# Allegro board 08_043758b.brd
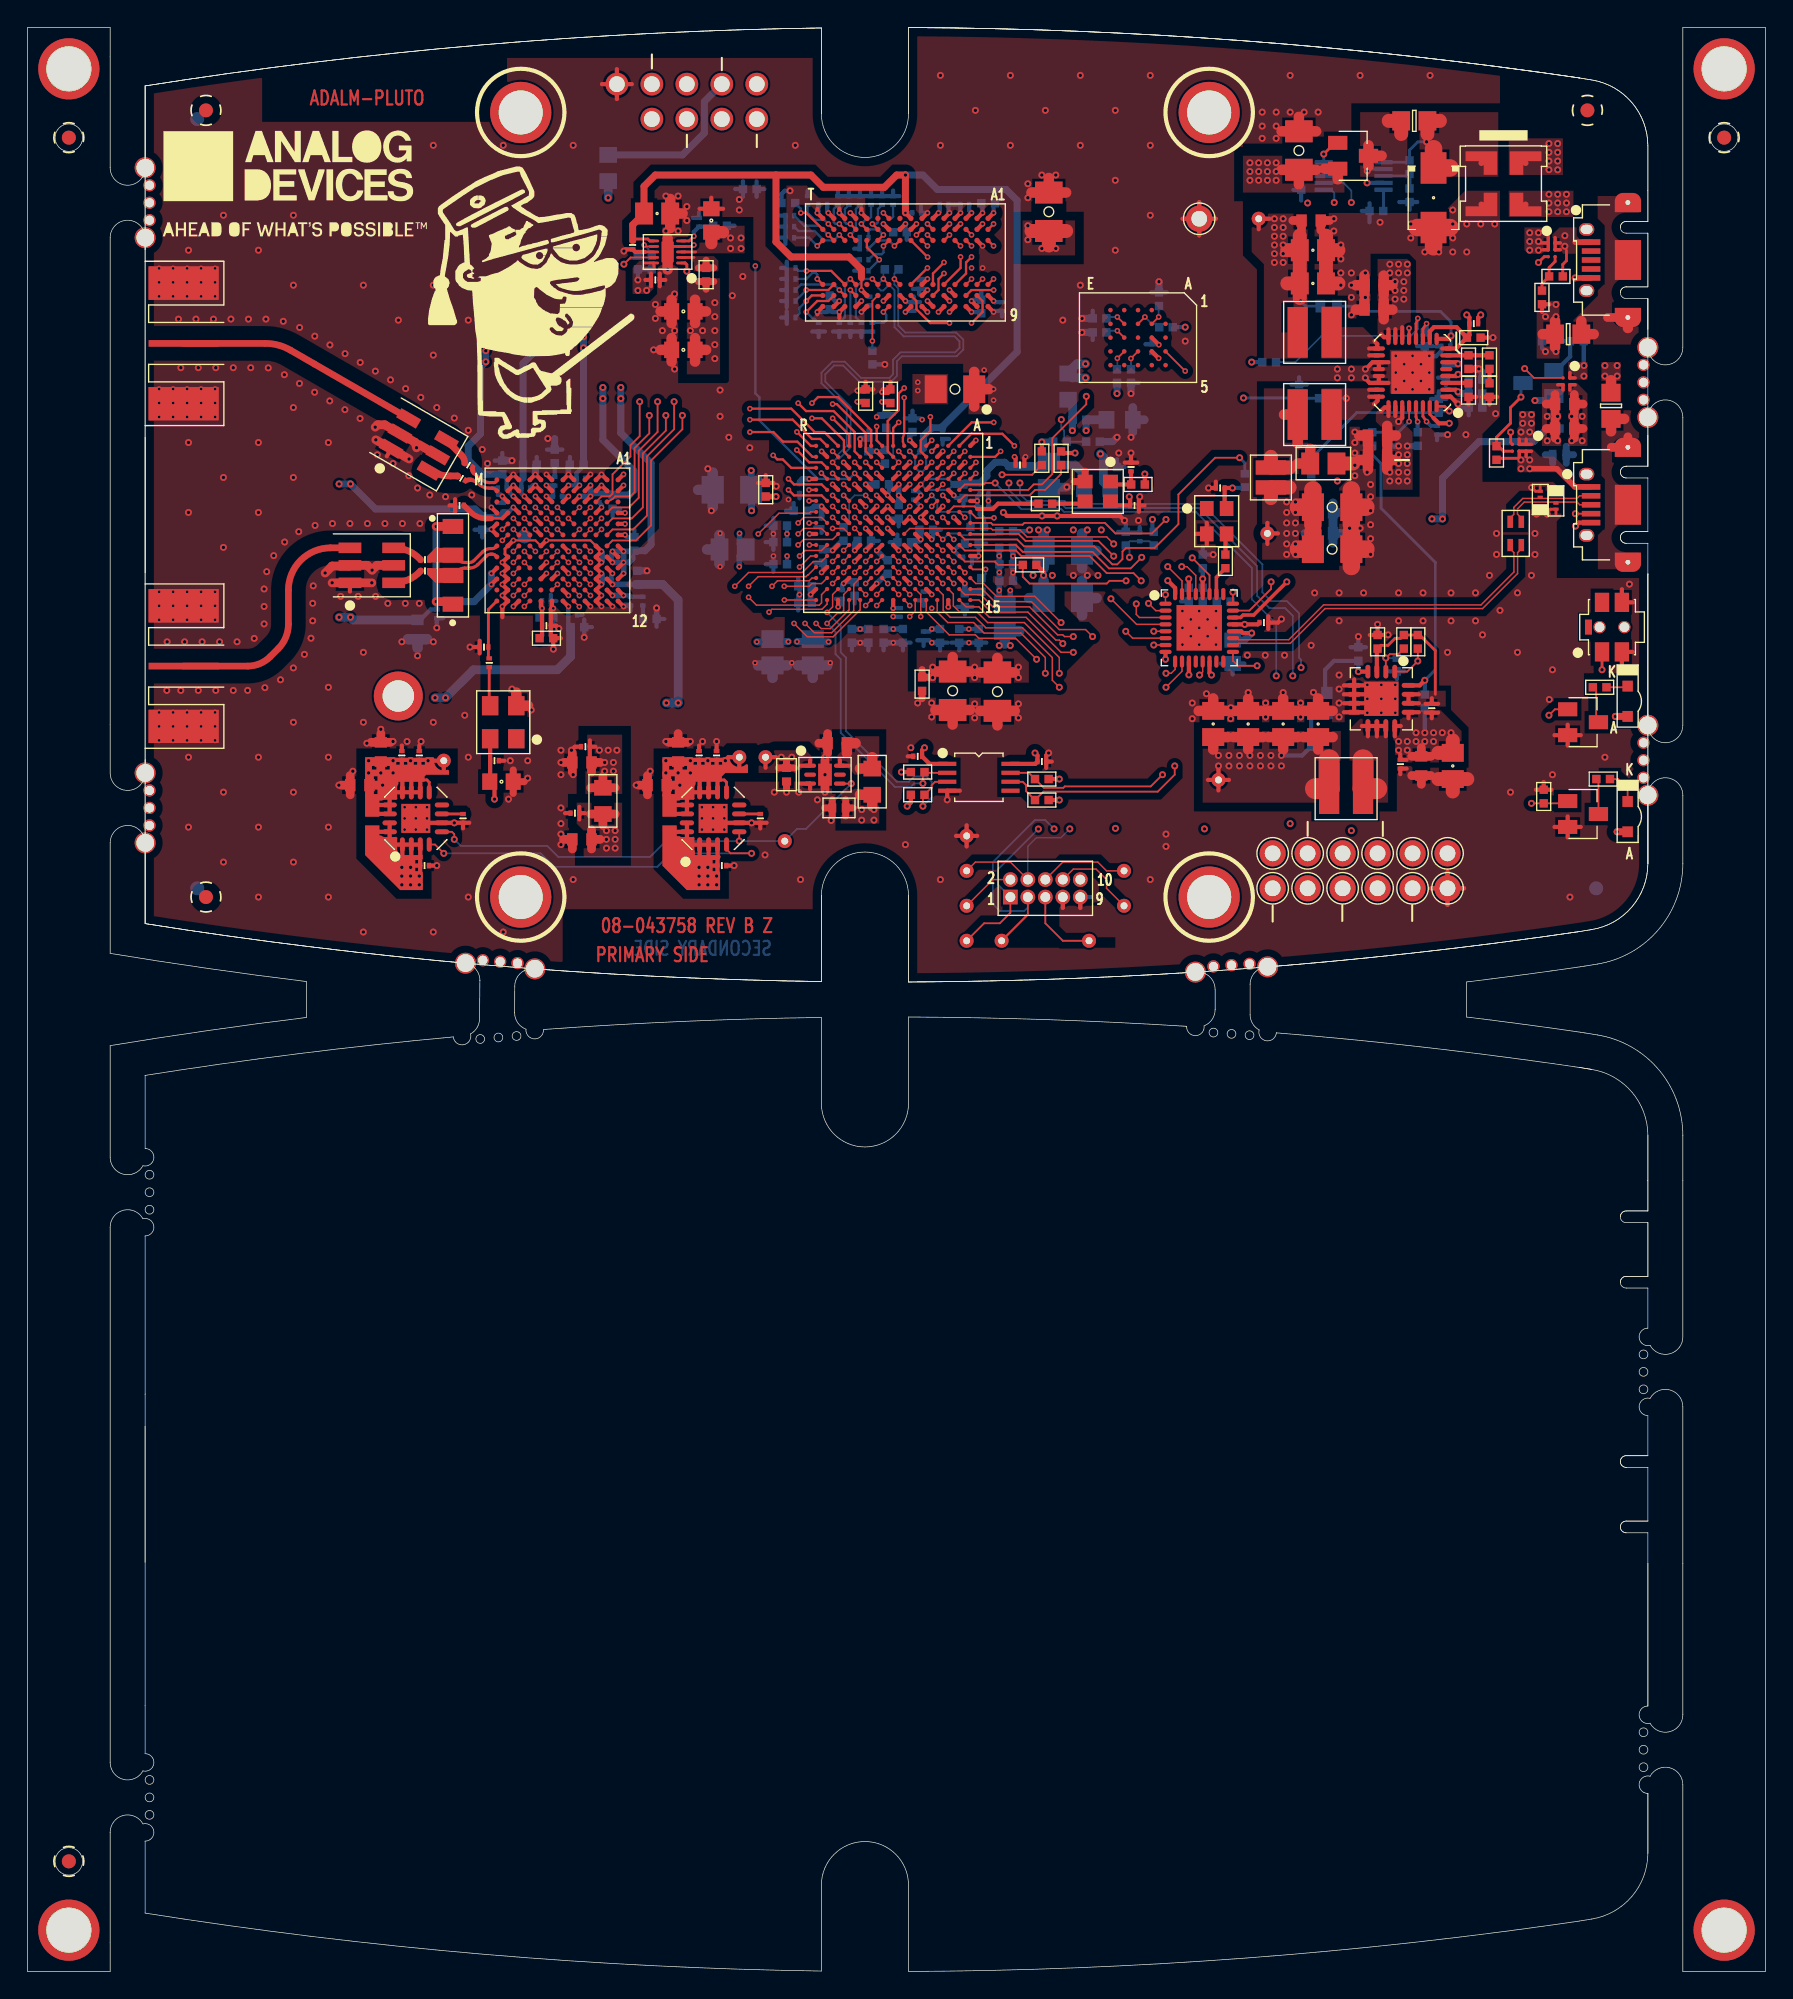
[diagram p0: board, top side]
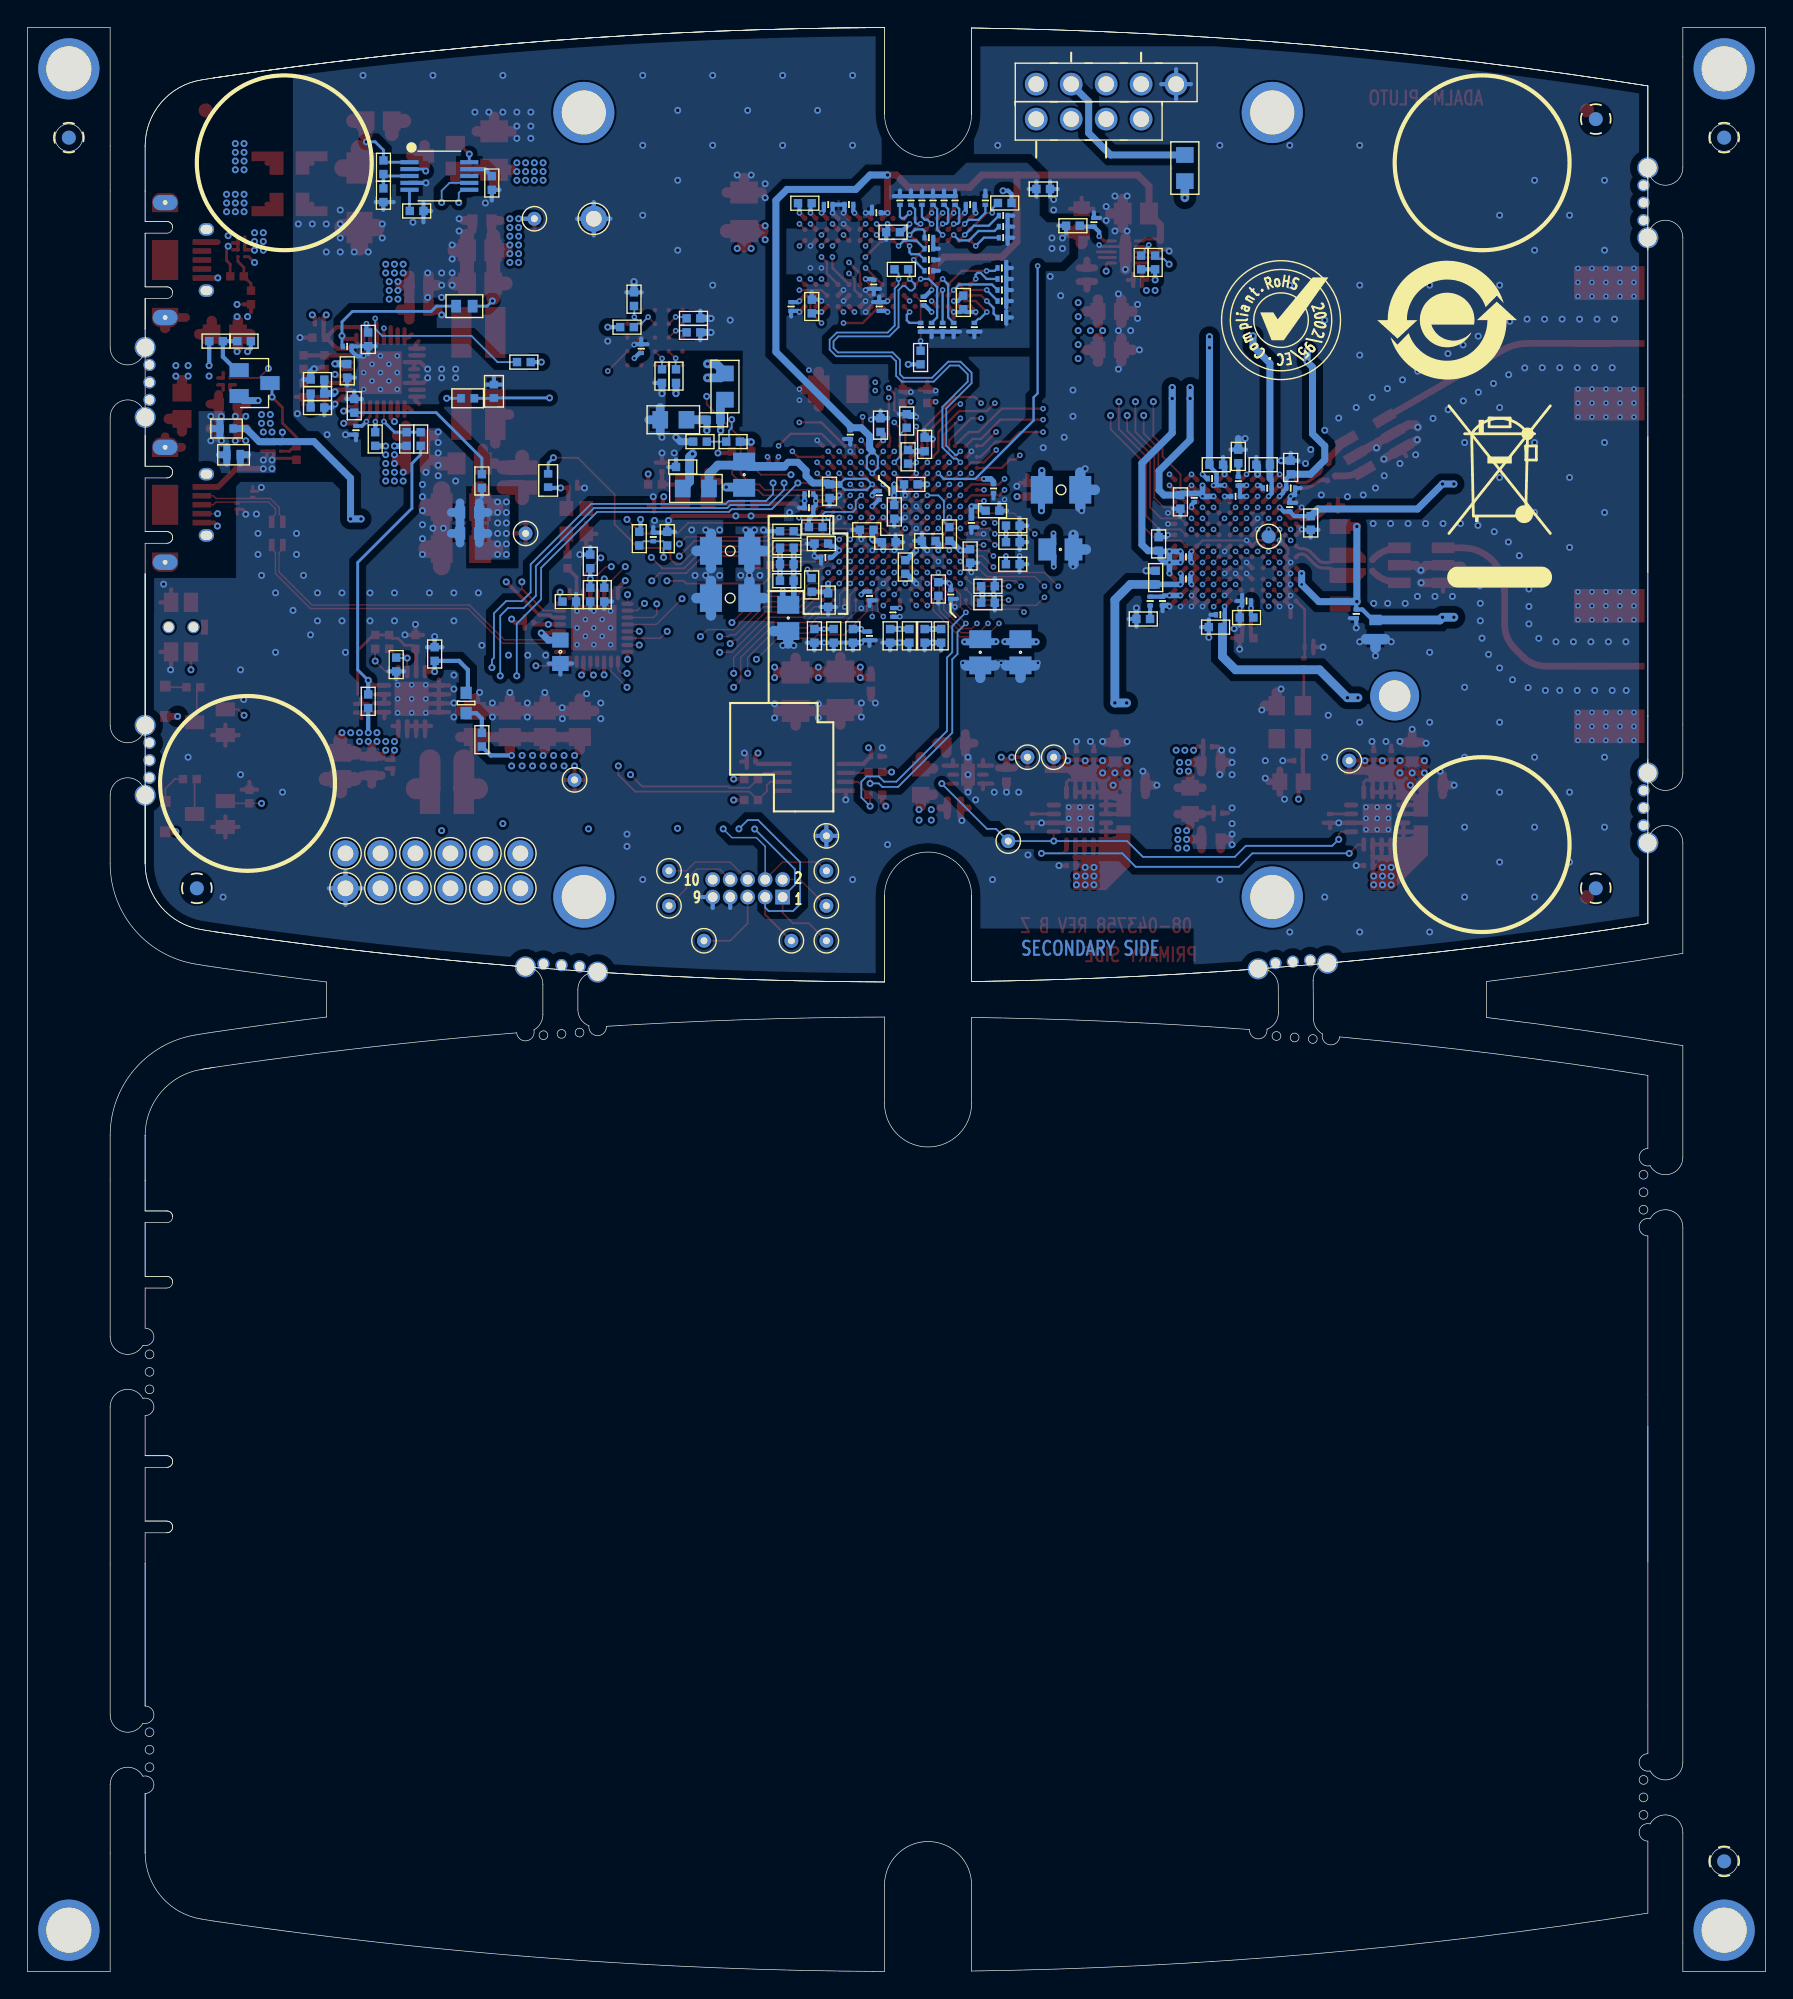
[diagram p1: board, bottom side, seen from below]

Outline 126.22 x 141.22 mm; copper layers: TOP, L2_GND, L3_PWR, L4_GND, L5_SIG, L6_SIG, L7_GND, L8_PWR, L9_GND, BOTTOM. Coordinates in mm from the lower left corner of the outline.

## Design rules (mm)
net group DDR3_CK: nets DDR3_CK_N DDR3_CK_P
net group DDR3_DQS0: nets DDR3_DQS0_N DDR3_DQS0_P
net group DDR3_DQS1: nets DDR3_DQS1_N DDR3_DQS1_P
net group DP1: nets UNNAMED_9_CHOKE4P_I327_N2 UNNAMED_9_CHOKE4P_I327_N3
net group RX1A: nets RX1A_N RX1A_P
net group TX1A: nets TX1A_N TX1A_P
net group UART: nets UART_RX UART_TX
net group USB_OTG: nets USB_OTG_N USB_OTG_P
net group CTRL_IN: nets CTRL_IN0 CTRL_IN1 CTRL_IN2 CTRL_IN3
net group CTRL_OUT: nets IO_L08_34_CTRL_OUT0 IO_L08_34_CTRL_OUT1 IO_L13_34_CTRL_OUT2 IO_L13_34_CTRL_OUT3 IO_L21_34_CTRL_OUT4 IO_L21_34_CTRL_OUT5 IO_L22_34_CTRL_OUT6 IO_L22_34_CTRL_OUT7
net group JTAG: nets JTAG_TCK JTAG_TDI JTAG_TDO JTAG_TMS
net group PWR: nets VCCPLL VDD33_USB VDDA1P1_RX_VCO VTTVREF
net group QSPI: nets PS_MIO01_500_QSPI0_SS_B PS_MIO02_500_QSPI0_IO0 PS_MIO03_500_QSPI0_IO1 PS_MIO04_500_QSPI0_IO2 PS_MIO05_500_QSPI0_IO3 PS_MIO06_500_QSPI0_SCLK
net group RF: nets UNNAMED_7_CAP_I39_N2 UNNAMED_7_CAP_I40_N2 UNNAMED_7_CAP_I51_N1 UNNAMED_7_CAP_I52_N1 UNNAMED_7_CNBNC5P_I57_CNTR UNNAMED_7_CNBNC5P_I58_CNTR
net group RX: nets IO_L01_34_RX_D0 IO_L01_34_RX_D1 IO_L02_34_RX_D2 IO_L02_34_RX_D3 IO_L03_34_RX_D4 IO_L03_34_RX_D5 IO_L04_34_RX_D6 IO_L04_34_RX_D7 IO_L05_34_RX_D8 IO_L05_34_RX_D9 IO_L06_34_RX_D10 IO_L06_34_RX_D11 IO_L07_34_RX_FRAME IO_L12_MRCC_34_DATA_CLK
net group SPI: nets IO_L23_35_SPI_CLK IO_L23_35_SPI_ENB IO_L24_35_SPI_DI IO_L24_35_SPI_DO
net group TX: nets IO_L01_34_FB_CLK IO_L09_34_TX_FRAME IO_L15_34_TX_D0 IO_L15_34_TX_D1 IO_L16_34_TX_D2 IO_L16_34_TX_D3 IO_L17_34_TX_D4 IO_L17_34_TX_D5 IO_L18_34_TX_D6 IO_L18_34_TX_D7 IO_L19_34_TX_D8 IO_L19_34_TX_D9 IO_L20_34_TX_D10 IO_L20_34_TX_D11
net group USB_ULPI: nets PS_MIO28_501_USB0_D4 PS_MIO29_501_USB0_DIR PS_MIO30_501_USB0_STP PS_MIO31_501_USB0_NXT PS_MIO32_501_USB0_D0 PS_MIO33_501_USB0_D1 PS_MIO34_501_USB0_D2 PS_MIO35_501_USB0_D3 PS_MIO36_501_USB0_CLK PS_MIO37_501_USB0_D5 PS_MIO38_501_USB0_D6 PS_MIO39_501_USB0_D7

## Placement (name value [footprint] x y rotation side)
AD9361_CLKOUT  TESTPAD  [TPSMC40]  36.09 104.25 180 bottom
ADC  613 001 111 21  [CNHDR1X1H344]  52.96 137.11 180 bottom
C1  0.1uF  [C0201]  28.83 80.34 0 top
C2  0.01uF  [C0201]  31.63 83.77 270 top
C3  10uF  [C0603]  24.13 86.18 180 top
C4  10uF  [C0603]  25.66 88.59 90 top
C5  0.1uF  [C0201]  27.18 88.34 90 top
C6  0.1uF  [C0201]  28.45 88.34 90 top
C7  0.1uF  [C0201]  102.37 111.96 90 bottom
C8  0.1uF  [C0201]  99.7 87.7 270 top
C9  10uF  [C0603]  101.22 87.58 270 top
C10  0.1uF  [C0201]  50.42 80.34 0 top
C11  47uF  [C0805H60]  103.51 87.58 270 top
C12  0.01uF  [C0201]  53.22 83.77 270 top
C13  0.1uF  [C0201#2]  98.05 96.59 90 top
C14  10uF  [C0603]  47.25 88.59 90 top
C15  10uF  [C0603]  45.72 86.18 180 top
C16  0.1uF  [C0201]  48.77 88.34 90 top
C17  47uF  [C0805H60]  91.19 90.62 90 top
C18  0.1uF  [C0201]  50.04 88.34 90 top
C19  47uF  [C0805H60]  86.11 90.62 90 top
C20  47uF  [C0805H60]  88.65 90.62 90 top
C21  47uF  [C0805H60]  93.73 90.62 90 top
C22  10uF  [C0603]  40.26 82.24 180 top
C23  0.01uF  [C0201]  40.19 108.46 0 bottom
C24  0.01uF  [C0201]  34.48 107.76 180 bottom
C25  0.1uF  [C0201]  39.75 84.15 180 top
C26  0.01uF  [C0201]  39.59 98.56 0 bottom
C27  0.01uF  [C0201]  42.08 102.76 180 bottom
C28  1uF  [C0402]  39.89 109.46 180 bottom
C29  1uF  [C0402]  34.48 109.26 90 bottom
C30  1uF  [C0402]  39.93 97.66 0 bottom
C31  1uF  [C0402]  44.07 103.71 90 bottom
C32  10uF  [C0603]  40.26 87.83 180 top
C33  0.1uF  [C0201]  40.52 88.97 180 top
C34  1uF  [C0402]  36.48 109.46 0 bottom
C35  1uF  [C0402]  44.29 101.26 90 bottom
C36  1uF  [C0402]  33.02 105.23 270 bottom
C37  1uF  [C0402]  42.49 106.76 270 bottom
C38  1uF  [C0402]  37.69 98.35 0 bottom
C39  0.01uF  [C0201]  36.18 107.76 0 bottom
C40  0.01uF  [C0201]  42.08 101.16 180 bottom
C41  0.01uF  [C0201]  34.55 106.37 90 bottom
C42  0.01uF  [C0201]  41.49 107.06 270 bottom
C43  0.01uF  [C0201]  37.68 97.76 0 top
C44  0.01uF  [C0201]  37.69 99.56 0 bottom
C45  1uF  [C0402]  37.68 96.86 0 top
C46  0.1uF  [C0201]  80.39 106.5 0 top
C47  0.1uF  [C0201]  80.78 104.21 90 bottom
C48  0.1uF  [C0201]  81.65 117.89 90 bottom
C49  100uF  [C1206H71]  75.19 103.2 0 bottom
C50  4.7uF  [C0402]  71.07 103.43 0 bottom
C51  0.47uF  [C0402]  56.14 106.12 180 bottom
C52  0.1uF  [C0201]  69.47 107.33 0 bottom
C53  0.01uF  [C0201]  69.47 106.33 0 bottom
C54  100uF  [C1206H71]  67.36 114.95 0 top
C55  4.7uF  [C0402]  64.27 112.33 90 bottom
C56  0.47uF  [C0402]  53.61 107.64 90 top
C57  0.47uF  [C0402]  62.67 114.43 90 top
C58  0.47uF  [C0402]  60.87 114.44 90 top
C59  0.47uF  [C0402]  61.07 110.93 90 bottom
C60  0.1uF  [C0201]  72.08 109.44 0 top
C61  0.01uF  [C0201]  56.06 107.73 270 bottom
C62  0.01uF  [C0201]  45.6 122.88 180 top
C63  0.01uF  [C0201]  64.57 127.76 180 bottom
C64  100uF  [C1206H71]  70.44 92.97 270 top
C65  47uF  [C0805H60]  57.03 95.83 270 bottom
C66  4.7uF  [C0402]  62.47 102.03 270 bottom
C67  4.7uF  [C0402]  61.07 97.03 270 bottom
C68  0.47uF  [C0402]  64.97 93.52 270 top
C69  0.47uF  [C0402]  68.57 103.73 0 bottom
C70  0.47uF  [C0402]  63.27 106.03 270 bottom
C71  100uF  [C1206H71]  67.19 93.04 270 top
C72  0.47uF  [C0402]  60.77 103.93 0 bottom
C73  4.7uF  [C0402]  62.07 108.03 0 bottom
C74  0.47uF  [C0402]  63.67 103.83 180 bottom
C75  0.47uF  [C0402]  65.27 104.73 0 bottom
C76  100uF  [C1206H71]  51.16 107.63 180 bottom
C77  47uF  [C0805H60]  51.21 103.3 180 bottom
C78  4.7uF  [C0402]  54.66 103.83 180 bottom
C79  10uF  [C0603#2]  49.66 127.2 90 top
C80  0.01uF  [C0201]  48.77 127.07 90 bottom
C81  0.22UF  [C0805]  45.72 127.71 0 top
C82  10uF  [C0603#2]  47.63 117.8 180 top
C83  10uF  [C0603#2]  47.63 120.6 180 top
C84  0.01uF  [C0201]  43.95 125.42 270 top
C85  47uF  [C0805H60]  74.18 108.73 270 bottom
C86  4.7uF  [C0402]  58.26 121.25 270 bottom
C87  4.7uF  [C0402]  69.27 120.95 90 bottom
C88  0.47uF  [C0402]  69.77 128.46 180 bottom
C89  0.47uF  [C0402]  63.36 126.35 0 bottom
C90  0.47uF  [C0402]  54.66 105.03 180 bottom
C91  0.1uF  [C0201]  64.36 120.95 90 bottom
C92  0.1uF  [C0201]  64.76 122.55 270 bottom
C93  0.47uF  [C0402]  76.4 112.72 0 bottom
C94  0.1uF  [C0201]  68.06 128.36 180 bottom
C95  0.1uF  [C0201]  66.56 128.36 0 bottom
C96  0.1uF  [C0201]  57.76 128.35 180 bottom
C97  0.1uF  [C0201]  70.77 120.95 270 bottom
C98  0.1uF  [C0201]  64.37 107.23 90 bottom
C99  0.01uF  [C0201]  66.46 111.65 90 bottom
C100  100uF  [C1206H71]  74.17 127.84 90 top
C101  4.7uF  [C0402]  52.45 129.49 180 bottom
C102  0.01uF  [C0201]  61.16 121.35 270 bottom
C103  47uF  [C0805H60]  70.97 98.33 270 bottom
C104  47uF  [C0805H60]  54.11 95.83 270 bottom
C105  4.7uF  [C0402]  63.57 97.03 270 bottom
C106  4.7uF  [C0402]  59.87 97.03 270 bottom
C107  4.7uF  [C0402]  69.07 97.03 270 bottom
C108  4.7uF  [C0402]  54.67 102.23 180 bottom
C109  0.47uF  [C0402]  62.17 97.03 270 bottom
C110  0.47uF  [C0402]  60.07 100.43 270 bottom
C111  0.47uF  [C0402]  68.07 99.62 270 bottom
C112  0.47uF  [C0402]  56.47 100.63 180 bottom
C113  0.47uF  [C0402]  67.67 97.03 270 bottom
C114  0.47uF  [C0402]  56.47 99.43 180 bottom
C115  0.47uF  [C0402]  66.28 97.03 270 bottom
C116  0.47uF  [C0402]  57.76 102.83 270 bottom
C117  0.1uF  [C0201]  65.07 97.03 270 bottom
C118  0.1uF  [C0201]  59.17 100.03 270 bottom
C119  0.01uF  [C0201]  63.37 98.73 270 bottom
C120  0.01uF  [C0201]  57.67 105.23 270 bottom
C121  10uF  [C0603#2]  34.42 86.43 0 top
C122  0.1uF  [C0201]  33.91 87.96 0 top
C123  18pF  [C0201]  33.53 95.07 90 top
C124  18pF  [C0201]  33.15 96.21 180 top
C125  0.001uF  [C0201]  38.48 107.16 180 bottom
C126  1uF  [C0402]  38.28 110.06 270 bottom
C127  1uF  [C0402]  45.19 98.25 0 bottom
C128  0.001uF  [C0201]  43.79 99.55 270 bottom
C129  0.001uF  [C0201]  29.72 98.63 90 bottom
C130  10uF  [C0603]  28.32 97.48 270 bottom
C131  18pF  [C0201]  28.86 101.74 180 top
C132  18pF  [C0201]  28.86 102.56 180 top
C133  18pF  [C0201]  31.52 108.47 330 top
C134  18pF  [C0201]  32.03 109.43 330 top
C135  10uF  [C0603]  98.05 111.58 180 top
C136  10uF  [C0603]  97.79 120.72 180 top
C137  10uF  [C0603]  98.05 109.8 180 top
C138  10uF  [C0603]  97.79 122.5 180 top
C139  0.047uF  [C0402]  101.48 118.56 90 bottom
C140  1uF  [C0402]  85.35 102.44 90 bottom
C141  1uF  [C0402]  105.03 118.69 0 top
C142  150pF  [C0402]  105.16 115.64 180 bottom
C143  180pF  [C0402]  104.65 116.91 90 top
C144  0.0033uF  [C0402]  106.18 116.91 270 top
C145  47uF  [C0805H60]  93.35 125.04 0 top
C146  22uF  [C0805H53]  94.11 109.55 0 top
C147  0.0056uF  [C0402]  105.16 113.61 0 bottom
C148  47uF  [C0805H60]  93.35 122.63 0 top
C149  100uF  [C1206H71]  94.75 103.32 0 top
C150  100uF  [C1206H71]  94.75 106.37 0 top
C151  10uF  [C0603]  93.22 127.2 0 top
C152  10uF  [C0603]  94.11 105.99 0 bottom
C153  10uF  [C0603]  94.11 104.47 0 bottom
C154  1uF  [C0402]  84.33 100.02 270 bottom
C155  0.047uF  [C0402]  92.5 129.93 270 bottom
C156  0.47uF  [C0402]  97.96 127.89 180 bottom
C157  100uF  [C1206H71]  92.33 132.28 90 top
C158  100uF  [C1206H71]  75.19 99.77 0 bottom
C159  4.7uF  [C0402]  71.07 102.23 0 bottom
C160  0.47uF  [C0402]  71.07 101.03 0 bottom
C161  0.1uF  [C0201]  65.07 99.93 270 bottom
C162  0.01uF  [C0201]  68.27 102.73 0 bottom
C163  0.1uF  [C0201]  86.62 107.77 0 top
C164  0.1uF  [C0201]  89.79 97.99 0 top
C165  2.2uF  [C0603#2]  87.52 95.87 270 bottom
C166  0.1uF  [C0201]  64.65 88.27 0 top
C167  0.1uF  [C0201]  73.66 87.89 0 top
C168  1uF  [C0402]  85.35 100.02 270 bottom
C169  1uF  [C0402]  58.93 84.53 180 top
C170  1uF  [C0402]  55.12 86.94 270 top
C171  2.2uF  [C0603]  111.64 113.87 180 top
C172  2.2uF  [C0603]  111.64 112.09 180 top
C173  10uF  [C0603]  58.8 89.23 180 top
C174  4.7uF  [C0402]  78.63 109.29 0 bottom
C178  0.47uF  [C0402]  67.98 107.54 270 bottom
D1  SESD0201X1UN-0020-09  [D0201]  111 106.45 270 top
D2  SESD0201X1UN-0020-09  [D0201]  109.86 107.31 90 top
D3  SMAJ5A  [DIOSMJ5_0]  102.11 128.85 270 top
DAC1  613 001 111 21  [CNHDR1X1H344]  45.34 137.11 180 bottom
DAC2  613 001 111 21  [CNHDR1X1H344]  45.34 134.57 180 bottom
DS1  LTST-S220TBKT  [LED0804]  116.21 92.28 270 top
DS2  LTST-S220TBKT  [LED0804]  116.21 83.89 270 top
E1  100OHM  [L0805]  77.68 107.73 180 bottom
E2  100OHM  [L0805]  61.34 86.43 90 top
E3  100OHM  [L0805]  42.17 131.01 270 bottom
E4  100OHM  [L0805]  41.79 85.04 90 top
E5  100OHM  [L0805]  75.57 115.14 270 bottom
E6  100OHM  [L0805]  79.32 112.72 180 bottom
F1  0.5A  [F0402H20]  111.26 110.18 180 bottom
GND  TESTPAD  [unnamed#3]  68.2 82.5 180 bottom
GND#2  613 001 111 21  [unnamed#3]  42.8 137.11 180 bottom
GND#3  WP45  [unnamed#3]  85.09 127.33 180 bottom
GND#4  WP45  [unnamed#3]  103.13 78.69 180 bottom
GPO0  613 001 111 21  [CNHDR1X1H344]  52.96 134.57 180 bottom
GPO1  613 001 111 21  [CNHDR1X1H344]  50.42 134.57 180 bottom
GPO2  613 001 111 21  [CNHDR1X1H344]  47.88 134.57 180 bottom
GPO3  613 001 111 21  [CNHDR1X1H344]  47.88 137.11 180 bottom
JTAG_BOOT  TESTPAD  [TPSMC40]  77.09 74.88 180 bottom
L2  1.5uH  [LSMSQ157H83]  93.48 119.07 180 top
L3  1.5uH  [LSMSQ157H83]  93.48 113.1 180 top
L4  1uH  [LSMSQ157H83]  95.76 85.93 180 top
L5  270NH  [LSMSQ79H41]  90.3 108.53 270 top
L6  90OHMS AT 100MEGHZ  [L0805-4PH39]  108.08 104.47 90 top
L7  800OHMS AT 100MEGHZ  [L2020_A]  107.19 129.87 180 top
L8  330NH  [L0805-F]  30.9 100.37 90 top
L9  330NH  [L0805-F]  30.9 103.93 270 top
L10P  WP45  [TPC75D45]  90.43 78.69 180 bottom
L12N  WP45  [TPC75D45]  92.97 78.69 180 bottom
L24N  WP45  [TPC75D45]  90.43 81.23 180 bottom
MIO0  WP45  [TPC75D45]  100.59 81.23 180 bottom
MIO09  WP45  [TPC75D45]  98.05 78.69 180 bottom
MIO10  WP45  [TPC75D45]  100.59 78.69 180 bottom
MIO11  WP45  [TPC75D45]  98.05 81.23 180 bottom
MIO48  WP45  [TPC75D45]  92.97 81.23 180 bottom
MIO49  WP45  [TPC75D45]  95.51 78.69 180 bottom
MIO53  WP45  [TPC75D45]  95.51 81.23 180 bottom
NOREF  -  [unnamed]  117.36 116.71 0 top
NOREF#2  -  [unnamed]  3 3 180 top
NOREF#3  -  [#2]  7.27 125.95 0 top
NOREF#4  -  [#2]  -91.18 -74.35 0 top
NOREF#5  -  [unnamed]  34.33 73.36 0 top
NOREF#6  -  [#2]  -91.18 -74.35 0 top
NOREF#7  -  [unnamed]  8.86 127.22 0 top
NOREF#8  -  [#2]  7.27 10.11 0 top
NOREF#9  -  [unnamed]  90.06 72.98 0 top
NOREF#10  -  [unnamed]  117.36 86.72 0 top
NOREF#11  -  [unnamed]  123.22 138.22 180 top
NOREF#12  -  [#2]  3 138.22 0 top
NOREF#13  -  [unnamed]  8.86 129.76 0 top
NOREF#14  -  [#2]  403.09 237.99 0 top
NOREF#15  -  [unnamed]  35.58 73.25 0 top
NOREF#16  -  [unnamed]  8.86 128.49 0 top
NOREF#17  -  [unnamed]  31.81 73.25 0 top
NOREF#18  -  [#2]  3 3 0 top
NOREF#19  -  [#2]  0 0 0 top
NOREF#20  -  [unnamed]  87.44 73.11 0 top
NOREF#21  -  [#2]  8.54 4.24 0 top
NOREF#22  -  [unnamed]  8.86 83.26 0 top
NOREF#23  -  [#2]  7.27 15.19 0 top
NOREF#24  -  [unnamed]  117.36 115.44 0 top
NOREF#25  -  [unnamed]  12.96 135.2 0 top
NOREF#26  -  [unnamed]  117.36 114.17 0 top
NOREF#27  -  [#2]  104.5 69.34 0 top
NOREF#28  -  [unnamed]  35.82 78.05 180 top
NOREF#29  -  [unnamed]  113.29 135.2 0 top
NOREF#30  -  [#2]  -80.18 88.52 0 top
NOREF#31  -  [unnamed]  26.93 92.66 0 top
NOREF#32  -  [unnamed]  117.68 90.53 0 top
NOREF#33  -  [unnamed]  33.07 73.46 0 top
NOREF#34  -  [unnamed]  117.68 112.9 0 top
NOREF#35  -  [#2]  7.27 87.07 0 top
NOREF#36  -  [unnamed]  36.84 72.83 0 top
NOREF#37  -  [unnamed]  8.86 84.53 0 top
NOREF#38  -  [unnamed]  84.82 72.6 0 top
NOREF#39  -  [unnamed]  85.82 135.05 180 top
NOREF#40  -  [#2]  7.27 59.15 0 top
NOREF#41  -  [#2]  126.22 0 90 top
NOREF#42  -  [#2]  0 141.22 0 top
NOREF#43  -  [#2]  7.27 81.99 0 top
NOREF#44  -  [unnamed]  35.82 135.05 180 top
NOREF#45  -  [unnamed]  86.13 73.01 0 top
NOREF#46  -  [#2]  123.22 3 0 top
NOREF#47  -  [unnamed]  117.36 87.99 0 top
NOREF#48  -  [#2]  19.43 129.87 0 top
NOREF#49  -  [#2]  124.53 139.17 0 top
NOREF#50  -  [#2]  -91.18 -74.35 0 top
NOREF#51  -  [#2]  6 0 0 top
NOREF#52  -  [unnamed]  3 133.22 0 top
NOREF#53  -  [unnamed]  12.96 78.05 0 top
NOREF#54  -  [unnamed]  123.22 3 180 top
NOREF#55  -  [#2]  3 3 0 top
NOREF#56  -  [#2]  120.22 0 0 top
NOREF#57  -  [#2]  126.22 0 0 top
NOREF#58  -  [unnamed]  117.36 89.26 0 top
NOREF#59  -  [unnamed]  8.54 81.99 0 top
NOREF#60  -  [#2]  7.27 54.07 0 top
NOREF#61  -  [#2]  210.84 143.3 0 top
NOREF#62  -  [#2]  0 141.22 0 top
NOREF#63  -  [unnamed]  8.54 131.03 0 top
NOREF#64  -  [#2]  36.58 121.23 0 top
NOREF#65  -  [#2]  0 0 0 top
NOREF#66  -  [unnamed]  3 8 0 top
NOREF#67  -  [unnamed]  88.75 73.2 0 top
NOREF#68  -  [unnamed]  3 138.22 180 top
NOREF#69  -  [unnamed]  8.54 125.95 0 top
NOREF#70  -  [unnamed]  85.82 78.05 180 top
NOREF#71  -  [#2]  117.68 8.61 0 top
NOREF#72  -  [unnamed]  123.22 133.22 0 top
NOREF#73  -  [#2]  -29.22 306.96 0 top
NOREF#74  -  [unnamed]  117.68 85.45 0 top
NOREF#75  -  [#2]  7.27 131.03 0 top
NOREF#76  -  [unnamed]  8.54 87.07 0 top
NOREF#77  -  [#2]  20.27 69.31 0 top
NOREF#78  -  [#2]  124.21 133.37 0 top
NOREF#79  -  [unnamed]  8.86 85.8 0 top
NOREF#80  -  [unnamed]  117.68 117.98 0 top
NOREF#81  -  [unnamed]  12.32 134.57 180 bottom
NOREF#82  -  [#2]  23.12 119.96 180 bottom
NOREF#83  -  [unnamed]  3 8 180 bottom
NOREF#84  -  [unnamed]  3 133.22 180 bottom
NOREF#85  -  [#2]  35.18 119.96 180 bottom
NOREF#86  -  [unnamed]  113.92 78.69 180 bottom
NOREF#87  -  [#2]  10.04 117.42 180 bottom
NOREF#88  -  [unnamed]  123.22 133.22 180 bottom
NOREF#89  -  [unnamed]  12.32 78.69 180 bottom
P1  FTSH-105-01-L-D  [CNHDR2X5H219]  71.38 78.05 0 top
P2  47590-0001  [CNMOLEX47590-0001]  117.68 106.55 180 top
P3  47590-0001  [CNMOLEX47590-0001]  117.68 124.33 180 top
PG_1P3V  TESTPAD  [TPSMC40]  54.99 82.12 180 bottom
Q1  BSS138LT1G  [SOT23]  112.97 90.75 270 top
Q2  BSS138LT1G  [SOT23]  109.73 115.39 270 bottom
Q3  SI2304DDS-T1-GE3  [SOT23]  96.27 131.9 270 top
Q4  BSS138LT1G  [SOT23]  112.97 84.08 270 top
R1  10  [R0201]  101.98 91.77 270 top
R2  27.4K  [R0402]  96.65 95.7 270 bottom
R3  46.4K  [R0402]  99.44 94.94 90 bottom
R4  17.8K  [R0603]  94.36 92.15 270 bottom
R5  0  [R0402]  100.97 96.59 270 top
R6  10K  [R0402]  101.48 92.28 90 bottom
R7  1K  [R0402]  93.22 89.48 270 bottom
R8  10K  [R0402]  80.65 108.02 180 top
R9  10K  [R0201]  80.14 109.29 90 top
R10  0  [R0402]  99.95 96.59 270 top
R11  4.7K  [R0402]  74.98 111.14 0 bottom
R12  39  [R0402]  73.92 106.63 180 top
R13  20K  [R0402]  81.79 104.09 270 bottom
R14  240  [R0402]  82.68 119.45 180 bottom
R15  0  [R0402]  79.76 104.09 90 bottom
R16  120  [R0201]  60.46 128.65 90 bottom
R17  120  [R0201]  55.36 126.76 180 bottom
R18  120  [R0201]  55.45 122.15 180 bottom
R19  120  [R0201]  57.46 119.45 270 bottom
R20  120  [R0201]  55.46 120.15 180 bottom
R21  120  [R0201]  60.56 119.45 270 bottom
R22  120  [R0201]  55.46 123.75 180 bottom
R23  120  [R0201]  59.66 128.65 90 bottom
R24  120  [R0201]  58.86 128.65 90 bottom
R25  120  [R0201]  56.66 128.65 90 bottom
R26  120  [R0201]  55.36 127.56 180 bottom
R27  120  [R0201]  55.45 121.35 180 bottom
R28  120  [R0201]  58.96 119.45 270 bottom
R29  120  [R0201]  55.46 122.95 180 bottom
R30  120  [R0201]  59.76 119.45 270 bottom
R31  120  [R0201]  60.76 125.95 180 bottom
R32  120  [R0201]  60.76 124.35 180 bottom
R33  120  [R0201]  62.86 128.65 90 bottom
R34  120  [R0201]  55.36 125.95 180 bottom
R35  120  [R0201]  61.26 128.65 90 bottom
R36  120  [R0201]  60.76 123.55 180 bottom
R37  120  [R0201]  60.76 125.15 180 bottom
R38  120  [R0201]  61.36 119.45 270 bottom
R39  120  [R0201]  62.06 128.65 90 bottom
R40  240  [R0402]  62.37 112.63 90 bottom
R41  240  [R0402]  62.27 110.03 90 bottom
R42  1K  [R0402]  55.25 128.47 180 bottom
R43  0  [R0402]  50.3 126.82 180 bottom
R44  0  [R0402]  49.28 123.26 90 top
R45  0  [R0402]  68.97 104.93 180 bottom
R46  4.7K  [R0402]  59.27 104.43 270 bottom
R47  4.7K  [R0402]  73.66 109.93 90 top
R48  470  [R0402]  114.18 93.29 180 top
R49  14.3K  [R0201]  31.37 106.5 0 top
R50  100K  [R0402]  90.17 116.91 180 bottom
R51  1  [R0201]  38.28 108.26 270 bottom
R52  1  [R0201]  44.69 99.55 270 bottom
R53  27.4K  [R0402]  104.65 114.88 90 top
R54  4.7K  [R0402]  103 116.28 270 bottom
R55  1K  [R0805]  115 113.74 90 top
R56  10  [R0201]  105.03 119.71 180 top
R57  20K  [R0402]  88.41 108.31 90 bottom
R58  1K  [R0805]  111.89 118.95 180 top
R59  100K  [R0402]  100.97 111.33 270 bottom
R60  10K  [R0402]  105.16 114.63 0 bottom
R61  10K  [R0402]  106.18 114.88 90 top
R62  17.8K  [R0603#2]  94.49 120.98 0 bottom
R63  14.3K  [R0201]  103 118.06 180 bottom
R64  46.4K  [R0402]  93.22 108.28 270 bottom
R65  23.2K  [R0402]  102.49 113.74 270 bottom
R66  240  [R0402]  112.53 118.44 180 bottom
R67  10K  [R0402]  110.49 118.44 180 bottom
R68  10K  [R0402]  111 123.14 180 top
R69  10K  [R0402]  109.99 121.61 270 top
R70  10K  [R0402]  106.68 110.31 90 top
R71  10K  [R0402]  100.37 131.07 270 bottom
R72  10K  [R0402]  100.37 129.04 270 bottom
R73  0.05  [R0805]  100.71 134.44 180 top
R74  10K  [R0402]  72.77 102.18 180 top
R75  10K  [R0402]  110.11 85.35 90 top
R76  20K  [R0402]  69.27 100.73 90 bottom
R77  8.06K  [R0402]  86.87 99.51 180 bottom
R78  4.7K  [R0402]  64.65 85.48 0 top
R79  4.7K  [R0402]  64.65 87.13 0 top
R80  4.7K  [R0402]  73.66 85.1 180 top
R81  4.7K  [R0402]  73.66 86.62 180 top
R82  39  [R0402]  87 102.44 90 top
R83  20K  [R0402]  71.07 104.63 180 bottom
R84  20K  [R0402]  75.06 109.93 90 top
R85  0  [R0402]  98.68 111.33 90 bottom
R86  0  [R0402]  97.67 111.33 90 bottom
R87  470  [R0402]  114.43 86.62 180 top
R88  1K  [R0402]  111.76 112.09 180 bottom
R89  4.7K  [R0402]  94.25 114.28 180 bottom
R90  1K  [R0402]  92.35 114.79 90 bottom
R91  4.7K  [R0402]  77.38 111.14 0 bottom
R116  20K  [R0402]  82.17 121.49 90 bottom
R119  20K  [R0402]  77.85 120.09 180 bottom
R120  20K  [R0402]  77.85 119.07 180 bottom
R121  20K  [R0402]  80.14 115.9 270 bottom
R122  20K  [R0402]  79.12 115.9 270 bottom
R142  80.6  [R0402]  62.76 123.65 180 bottom
R165  240  [R0402]  61.36 117.25 270 bottom
R221  10K  [R0402]  44.33 124.15 90 bottom
R222  10K  [R0402]  45.34 124.15 90 bottom
RX  TESTPAD  [TPSMC40]  68.2 74.88 180 bottom
RX1A  JCCEM001  [CNSMARAL687W375H171]  11.08 118.27 180 top
S1  PTS840 GKP SMTR LFS  [SWSML140W138H55]  115.07 97.66 0 top
T1  TCM1-63AX+  [TSML150W160H160]  28.42 110.93 60 top
T5  TCM1-63AX+  [TSML150W160H160]  25 102.15 90 top
TCK  TESTPAD  [TPSMC40]  68.2 79.96 180 bottom
TDI  TESTPAD  [TPSMC40]  79.63 77.42 180 bottom
TDO  TESTPAD  [TPSMC40]  79.63 79.96 180 bottom
TMS  TESTPAD  [TPSMC40]  68.2 77.42 180 bottom
TX  TESTPAD  [TPSMC40]  70.74 74.88 180 bottom
TX1A  JCCEM001  [CNSMARAL687W375H171]  11.08 94.83 180 top
U1  ADP1754ACPZ-1.3  [QFN16_4X4_PAD2_1X2_1]  28.2 83.77 0 top
U2  MT41K256M16TW-107 IT:P  [FBGA96_C]  63.76 124.15 180 top
U3  ADP2164ACPZ  [QFN16_4X4_PAD2_5X2_5]  98.32 92.45 180 top
U4  XC7Z010-1CLG225C  [CSPBGA225]  62.87 105.23 180 top
U5  AD9363ABCZ  [BGA144-2]  38.48 103.96 180 top
U6  ADP2114ACPZ  [QFN32_5X5_PAD3_1X3_1]  100.59 116.15 90 top
U7  ADP1754ACPZ-1.3  [QFN16_4X4_PAD2_1X2_1]  49.79 83.77 0 top
U8  NCP339AFCT2G  [WLCSP6]  110.69 125.07 270 top
U9  NCP339AFCT2G  [WLCSP6]  108.33 110.69 180 top
U10  ADM1177-1ARMZ  [RM10]  96.31 130.43 270 bottom
U11  TCA9517DGKR  [MSOP8]  69.09 86.75 270 top
U12  ADM7160ACPZN1.8  [DFN6_2X2_PAD1_6X1]  57.92 86.94 270 top
U13  MT25QU256ABA8E12-1SIT  [TBGA24]  80.65 118.69 180 top
U14  TPS51206DSQR  [SON10_2X2_PAD1_5X0_9]  46.49 124.91 90 top
U15  USB3320C-EZK  [QFN32_5X5_PAD3_3X3_3]  85.09 97.61 270 top
U16  ADP198ACBZ-11  [WLCSP4-2]  111.76 115.52 180 top
UNK1P0V  TESTPAD  [TPSMC40]  86.49 86.56 180 bottom
UNK1P3V_A  TESTPAD  [TPSMC40]  51.69 88.21 180 bottom
UNK1P3V_B  TESTPAD  [TPSMC40]  30.23 87.96 180 bottom
UNK1P8V_CLK  TESTPAD  [TPSMC40]  53.6 88.21 180 bottom
UNK1V8  TESTPAD  [TPSMC40]  103.13 81.23 180 bottom
UNK1V8#2  TESTPAD  [TPSMC40]  90.05 104.47 180 bottom
UNK1V35  TESTPAD  [TPSMC40]  89.41 127.33 180 bottom
VDD_GPO  613 001 111 21  [CNHDR1X1H344]  50.42 137.11 180 bottom
Y1  24MEGHZ  [YSML98W79H35]  86.36 105.36 270 top
Y2  33.333MEGHZ  [YSML98W79H35]  77.73 107.52 180 top
Y3  40MEGHz  [YSML126W98H47]  34.55 90.75 90 top

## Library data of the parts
AD9361_CLKOUT JTAG_BOOT PG_1P3V RX TCK TDI TDO TMS TX UNK1P0V UNK1P3V_A UNK1P3V_B UNK1P8V_CLK UNK1V8 UNK1V35 = NCTESTPAD: Tolerance: N/A; User Part Number: UPN; alternate symbols: (); part number: NCTESTPAD_SM-TESTPAD,E019801,TPSMC40; tolerance: N/A
ADC DAC1 DAC2 GPO0-GPO3 VDD_GPO = CN1P: User Part Number: UPN; Tolerance: N/A; alternate symbols: (); part number: CN1P_TH-613 001 111 21,E016125,CNHDR1X1H344; tolerance: N/A
C1 C5-C8 C10 C16 C18 C25 C33 C46-C48 C52 C60 C91 C92 C94-C98 C117 C118 C122 C161 C163 C164 C166 C167 = CAP: User Part Number: UPN; Tolerance: 20; part number: CAP_SM-0.1UF,16V,20,E017331,C0201; tolerance: 20
C2 C12 C23 C24 C26 C27 C39-C44 C53 C61-C63 C80 C84 C99 C102 C119 C120 C162 = CAP: User Part Number: UPN; Tolerance: 10; part number: CAP_SM-0.01UF,10V,10,E007201,C0201; tolerance: 10
C3 C4 C9 C14 C15 C22 C32 C79 C82 C83 C121 C130 C135-C138 C151-C153 C173 = CAP: Tolerance: 20; User Part Number: UPN; alternate symbols: C0603L_ALT; part number: CAP_SM-10UF,6.3V,20,E007143,C0603; tolerance: 20
C11 C17 C19-C21 C65 C77 C85 C103 C104 C145 C148 = CAP: Tolerance: 20; User Part Number: UPN; alternate symbols: (); part number: CAP_SM-47UF,6.3V,20,E008247,C0805H60; tolerance: 20
C13 = CAP: Tolerance: 20; User Part Number: UPN; alternate symbols: C0402_ALT; part number: CAP_SM-0.1UF,16V,20,E017331,C0201; tolerance: 20
C28-C31 C34-C38 C45 C127 C140 C141 C154 C168 = CAP: Tolerance: 10; User Part Number: UPN; alternate symbols: C0402_ALT; part number: CAP_SM-1UF,6.3V,10,E007449,C0402; tolerance: 10
C49 C54 C64 C71 C76 C100 C149 C150 C157 C158 = CAP: Tolerance: 20; User Part Number: UPN; part number: CAP_SM-100UF,6.3V,20,E016591,C1206H71; tolerance: 20
C50 C55 C66 C67 C73 C78 C86 C87 C101 C105-C108 C159 C174 = CAP: Tolerance: 10; User Part Number: UPN; alternate symbols: C0402_ALT; part number: CAP_SM-4.7UF,6.3V,10,E020089,C0402; tolerance: 10
C51 C56-C59 C68-C70 C72 C74 C75 C88-C90 C93 C109-C116 C156 C160 C178 = CAP: Tolerance: 10; User Part Number: UPN; alternate symbols: C0402_ALT; part number: CAP_SM-0.47UF,10V,10,E007611,C0402; tolerance: 10
C81 = CAP: Tolerance: 10; User Part Number: UPN; part number: CAP_SM-0.22UF,16V,10,E000443,C0805; tolerance: 10
C123 C124 C131-C134 = CAP: User Part Number: UPN; Tolerance: 5; part number: CAP_SM-18PF,50V,5,E017960,C0201; tolerance: 5
C125 C128 C129 = CAP: User Part Number: UPN; Tolerance: 10; alternate symbols: (); part number: CAP_SM-0.001UF,25V,10,E006762,C0201; tolerance: 10
C126 = CAP: Tolerance: 10; User Part Number: UPN; alternate symbols: R0402_ALT; part number: CAP_SM-1UF,6.3V,10,E007449,C0402; tolerance: 10
C139 C155 = CAP: Tolerance: 10; User Part Number: UPN; alternate symbols: C0402_ALT; part number: CAP_SM-0.047UF,25V,10,E006454,C0402; tolerance: 10
C142 = CAP: Tolerance: 5; User Part Number: UPN; alternate symbols: C0402_ALT; part number: CAP_SM-150PF,50V,5,E012646,C0402; tolerance: 5
C143 = CAP: Tolerance: 5; User Part Number: UPN; alternate symbols: C0402_ALT; part number: CAP_SM-180PF,50V,5,E012612,C0402; tolerance: 5
C144 = CAP: Tolerance: 10; User Part Number: UPN; alternate symbols: C0402_ALT; part number: CAP_SM-0.0033UF,50V,10,E007461,C0402; tolerance: 10
C146 = CAP: Tolerance: 20; User Part Number: UPN; alternate symbols: (); part number: CAP_SM-22UF,6.3V,20,E006534,C0805H53; tolerance: 20
C147 = CAP: Tolerance: 10; User Part Number: UPN; alternate symbols: C0402_ALT; part number: CAP_SM-0.0056UF,25V,10,E011820,C0402; tolerance: 10
C165 = CAP: Tolerance: 10; User Part Number: UPN; alternate symbols: (); part number: CAP_SM-2.2UF,16V,10,E020871,C0603; tolerance: 10
C169 C170 = CAP: Tolerance: 10; User Part Number: UPN; alternate symbols: (); part number: CAP_SM-1UF,6.3V,10,E007449,C0402; tolerance: 10
C171 C172 = CAP: Tolerance: 10; User Part Number: UPN; alternate symbols: C0603L_ALT; part number: CAP_SM-2.2UF,16V,10,E020871,C0603; tolerance: 10
D1 D2 = DIO: Tolerance: N/A; User Part Number: UPN; alternate symbols: (); part number: DIO_SM-SESD0201X1UN-0020-09,9V,N/A,E022225,D0201; tolerance: N/A
D3 = DIO: Tolerance: N/A; User Part Number: UPN; alternate symbols: (); part number: DIO_SM-SMAJ5A,5V,N/A,E001108,DIOSMJ5_0; tolerance: N/A
DS1 DS2 = DIOLED: User Part Number: UPN; Tolerance: N/A; alternate symbols: LED0804_RA; part number: DIOLED_SM-LTST-S220TBKT,3.3V,N/A,E026167,LED0804; tolerance: N/A
E1-E6 = FERRITE: Tolerance: 25; User Part Number: UPN; alternate symbols: (); part number: FERRITE_SM-100OHM,25,E012241,L0805; tolerance: 25
F1 = FSFUSE: User Part Number: UPN; Tolerance: N/A; alternate symbols: (); part number: FSFUSE_SM-0.5A,6V,E023876,F0402H20; tolerance: N/A
GND GND#3 GND#4 UNK1V8#2 = -: Tolerance: N/A; User Part Number: UPN
GND#2 = -: User Part Number: UPN; Tolerance: N/A
L2 L3 = IND: User Part Number: UPN; Tolerance: 20; alternate symbols: (); part number: IND_SM-1.5UH,20,E017267,LSMSQ157H83; tolerance: 20
L4 = IND: User Part Number: UPN; Tolerance: 20; alternate symbols: (); part number: IND_SM-1UH,20,E015845,LSMSQ157H83; tolerance: 20
L5 = IND: User Part Number: UPN; Tolerance: 20; alternate symbols: (); part number: IND_SM-270NH,20,E027278,LSMSQ79H41; tolerance: 20
L6 = CHOKE4P: User Part Number: UPN; Tolerance: 25; alternate symbols: (); part number: CHOKE4P_SM-90OHMS AT 100MEGHZ,25,E027226,L0805-4PH39; tolerance: 25
L7 = CHOKE4P: User Part Number: UPN; Tolerance: N/A; alternate symbols: (); part number: CHOKE4P_SM-800OHMS AT 100MEGHZ,N/A,E027130,L2020_A; tolerance: N/A
L8 L9 = IND: Tolerance: 5; User Part Number: UPN; part number: IND_SM-330NH,5,E006599,L0805-F; tolerance: 5
L10P L12N L24N MIO0 MIO09-MIO11 MIO48 MIO49 MIO53 = NCWP: Tolerance: N/A; User Part Number: UPN; alternate symbols: (); part number: NCWP_TH-WP45,E002516,TPC75D45; tolerance: N/A
P1 = CN10P_ODD_EVEN: Tolerance: N/A; User Part Number: UPN; part number: CN10P_ODD_EVEN_TH-FTSH-105-01-L-D,E018623,CNHDR2X5H219; tolerance: N/A
P2 P3 = CN5P_3SHLD: User Part Number: UPN; Tolerance: N/A; alternate symbols: (); part number: CN5P_3SHLD_SM-47590-0001,E015753,CNMOLEX47590-0001; tolerance: N/A
Q1 Q2 Q4 = TRANNMOSFET_V8: User Part Number: UPN; Tolerance: N/A; part number: TRANNMOSFET_V8_SM-BSS138LT1G,E018770,SOT23; tolerance: N/A
Q3 = TRANTN0200T: User Part Number: UPN; Tolerance: N/A; alternate symbols: (); part number: TRANTN0200T_SM-SI2304DDS-T1-GE3,E014916,SOT23; tolerance: N/A
R1 R56 = RES: User Part Number: UPN; Tolerance: 1; part number: RES_SM-10,E013982,1/20W,1,R0201; tolerance: 1
R2 R53 = RES: Tolerance: 1; User Part Number: UPN; alternate symbols: R0402_ALT; part number: RES_SM-27.4K,E021819,1/10W,1,R0402; tolerance: 1
R3 R64 = RES: Tolerance: 1; User Part Number: UPN; alternate symbols: R0402_ALT; part number: RES_SM-46.4K,E011115,1/16W,1,R0402; tolerance: 1
R4 = RES: Tolerance: 1; User Part Number: UPN; alternate symbols: R0603_A; part number: RES_SM-17.8K,E011033,1/10W,1,R0603; tolerance: 1
R5 R10 R15 R43-R45 R85 R86 = RES: Tolerance: 1; User Part Number: UPN; alternate symbols: R0402_ALT; part number: RES_SM-0,E010661,1/16W,1,R0402; tolerance: 1
R6 R8 R60 R61 R67-R72 R74 R75 R221 R222 = RES: Tolerance: 1; User Part Number: UPN; alternate symbols: R0402_ALT; part number: RES_SM-10K,E003751,1/16W,1,R0402; tolerance: 1
R7 R42 = RES: Tolerance: 1; User Part Number: UPN; alternate symbols: R0402_ALT; part number: RES_SM-1K,E003763,1/10W,1,R0402; tolerance: 1
R9 = RES: User Part Number: UPN; Tolerance: 1; part number: RES_SM-10K,E004011,1/20W,1,R0201; tolerance: 1
R11 R46 R47 R54 R78-R81 R89 R91 = RES: Tolerance: 1; User Part Number: UPN; alternate symbols: R0402_ALT; part number: RES_SM-4.7K,E008190,1/16W,1,R0402; tolerance: 1
R12 R82 = RES: Tolerance: 5; User Part Number: UPN; alternate symbols: R0402_ALT; part number: RES_SM-39,E003441,1/16W,5,R0402; tolerance: 5
R13 R57 R76 R83 R84 R116 R119-R122 = RES: Tolerance: 1; User Part Number: UPN; alternate symbols: R0402_ALT; part number: RES_SM-20K,E003791,1/16W,1,R0402; tolerance: 1
R14 R40 R41 R66 R165 = RES: Tolerance: 1; User Part Number: UPN; alternate symbols: R0402_ALT; part number: RES_SM-240,E010877,1/16W,1,R0402; tolerance: 1
R16-R39 = RES: User Part Number: UPN; Tolerance: 1; part number: RES_SM-120,E011549,1/20W,1,R0201; tolerance: 1
R48 R87 = RES: Tolerance: 5; User Part Number: UPN; alternate symbols: R0402_ALT; part number: RES_SM-470,E017765,1/10W,5,R0402; tolerance: 5
R49 R63 = RES: User Part Number: UPN; Tolerance: 1; part number: RES_SM-14.3K,E014068,1/20W,1,R0201; tolerance: 1
R50 R59 = RES: Tolerance: 1; User Part Number: UPN; alternate symbols: R0402_ALT; part number: RES_SM-100K,E003796,1/16W,1,R0402; tolerance: 1
R51 R52 = RES: User Part Number: UPN; part number: RES_SM-1,E014056,1/20W,1,R0201
R55 R58 = RES: Tolerance: 1; User Part Number: UPN; alternate symbols: (); part number: RES_SM-1K,E023448,1/3W,1,R0805; tolerance: 1
R62 = RES: Tolerance: 1; User Part Number: UPN; alternate symbols: R0603L; part number: RES_SM-17.8K,E011033,1/10W,1,R0603; tolerance: 1
R65 = RES: Tolerance: 1; User Part Number: UPN; alternate symbols: R0402_ALT; part number: RES_SM-23.2K,E019517,1/16W,1,R0402; tolerance: 1
R73 = RES: Tolerance: 1; User Part Number: UPN; alternate symbols: (); part number: RES_SM-0.05,E013377,1/8W,1,R0805; tolerance: 1
R77 = RES: Tolerance: 1; User Part Number: UPN; alternate symbols: R0402_ALT; part number: RES_SM-8.06K,E021385,1/10W,1,R0402; tolerance: 1
R88 R90 = RES: Tolerance: 1; User Part Number: UPN; alternate symbols: (); part number: RES_SM-1K,E003763,1/10W,1,R0402; tolerance: 1
R142 = RES: Tolerance: 0.1; User Part Number: UPN; alternate symbols: R0402_ALT; part number: RES_SM-80.6,E022369,1/16W,0.1,R0402; tolerance: 0.1
RX1A TX1A = CNBNC5P: User Part Number: UPN; Tolerance: N/A; alternate symbols: (); part number: CNBNC5P_SM-JCCEM001,E027545,CNSMARAL687W375H171; tolerance: N/A
S1 = SWSPST5P_V2: User Part Number: UPN; Tolerance: N/A; alternate symbols: (); part number: SWSPST5P_V2_SM-PTS840 GKP SMTR LFS,E024294,SWSML140W138H55; tolerance: N/A
T1 T5 = XFMRTCMXXXX_V3: Tolerance: N/A; User Part Number: UPN; part number: XFMRTCMXXXX_V3_SM-TCM1-63AX+,E018203,TSML150W160H160; tolerance: N/A
U1 U7 = ADP1754: Tolerance: N/A; User Part Number: UPN; alternate symbols: (); part number: ADP1754_SM-ADP1754ACPZ-1.3,E022696,QFN16_4X4_PAD2_1X2_1; tolerance: N/A
U2 = ICMT41K256M16: User Part Number: UPN; Tolerance: N/A; alternate symbols: (); part number: ICMT41K256M16_SM-MT41K256M16TW-107 IT:P,E025601,FBGA96_C; tolerance: N/A
U3 = ADP2164: Tolerance: N/A; User Part Number: UPN; alternate symbols: (); part number: ADP2164_SM-ADP2164ACPZ,E013699,QFN16_4X4_PAD2_5X2_5; tolerance: N/A
U4 = ICXC7Z010: Tolerance: N/A; User Part Number: UPN; alternate symbols: (); part number: ICXC7Z010_SM-XC7Z010-1CLG225C,E025809,CSPBGA225; tolerance: N/A
U5 = AD9363: Tolerance: N/A; User Part Number: UPN; part number: AD9363_SM-AD9363ABCZ,E026056,BGA144-2; tolerance: N/A
U6 = ADP2114: User Part Number: UPN; Tolerance: N/A; alternate symbols: (); part number: ADP2114_SM-ADP2114ACPZ,E008105,QFN32_5X5_PAD3_1X3_1; tolerance: N/A
U8 U9 = ICNCP339: Tolerance: N/A; User Part Number: UPN; alternate symbols: (); part number: ICNCP339_SM-NCP339AFCT2G,E025896,WLCSP6; tolerance: N/A
U10 = ADM1177: Tolerance: N/A; User Part Number: UPN; alternate symbols: (); part number: ADM1177_SM-ADM1177-1ARMZ,E016506,RM10; tolerance: N/A
U11 = CMOSTCA9517: Tolerance: N/A; User Part Number: UPN; alternate symbols: (); part number: CMOSTCA9517_SM-TCA9517DGKR,E022173,MSOP8; tolerance: N/A
U12 = ADM7160_V2: User Part Number: UPN; Tolerance: N/A; alternate symbols: (); part number: ADM7160_V2_SM-ADM7160ACPZN1.8,E018693,DFN6_2X2_PAD1_6X1; tolerance: N/A
U13 = ICMT25Q: User Part Number: UPN; Tolerance: N/A; alternate symbols: (); part number: ICMT25Q_SM-MT25QU256ABA8E12-1SIT,E027529,TBGA24; tolerance: N/A
U14 = ICTPS51206: Tolerance: N/A; User Part Number: UPN; alternate symbols: (); part number: ICTPS51206_SM-TPS51206DSQR,E021346,SON10_2X2_PAD1_5X0_9; tolerance: N/A
U15 = ICUSB3320C: Tolerance: N/A; User Part Number: UPN; alternate symbols: (); part number: ICUSB3320C_SM-USB3320C-EZK,E021334,QFN32_5X5_PAD3_3X3_3; tolerance: N/A
U16 = ADP198: Tolerance: N/A; User Part Number: UPN; alternate symbols: (); part number: ADP198_SM-ADP198ACBZ-11,E024730,WLCSP4-2; tolerance: N/A
Y1 = XTALOSC4P_V7: Tolerance: N/A; User Part Number: UPN; alternate symbols: (); part number: XTALOSC4P_V7_SM-24MEGHZ,E022374,YSML98W79H35; tolerance: N/A
Y2 = XTALOSC4P_V7: Tolerance: N/A; User Part Number: UPN; part number: XTALOSC4P_V7_SM-33.333MEGHZ,E024048,YSML98W79H35; tolerance: N/A
Y3 = XTALOSC4P_V21: Tolerance: N/A; User Part Number: UPN; part number: XTALOSC4P_V21_SM-40MEGHZ,E020493,YSML126W98H47; tolerance: N/A

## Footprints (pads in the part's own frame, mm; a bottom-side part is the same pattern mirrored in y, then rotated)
BGA144-2
  round 0.356 smd: A1(-4.4,-4.4) A2(-4.4,-3.6) A3(-4.4,-2.8) A4(-4.4,-2) A5(-4.4,-1.2) A6(-4.4,-0.4) A7(-4.4,0.4) A8(-4.4,1.2) A9(-4.4,2) A10(-4.4,2.8) A11(-4.4,3.6) A12(-4.4,4.4) B1(-3.6,-4.4) B2(-3.6,-3.6) B3(-3.6,-2.8) B4(-3.6,-2) B5(-3.6,-1.2) B6(-3.6,-0.4) B7(-3.6,0.4) B8(-3.6,1.2) B9(-3.6,2) B10(-3.6,2.8) B11(-3.6,3.6) B12(-3.6,4.4) C1(-2.8,-4.4) C2(-2.8,-3.6) C3(-2.8,-2.8) C4(-2.8,-2) C5(-2.8,-1.2) C6(-2.8,-0.4) C7(-2.8,0.4) C8(-2.8,1.2) C9(-2.8,2) C10(-2.8,2.8) C11(-2.8,3.6) C12(-2.8,4.4) D1(-2,-4.4) D2(-2,-3.6) D3(-2,-2.8) D4(-2,-2) D5(-2,-1.2) D6(-2,-0.4) D7(-2,0.4) D8(-2,1.2) D9(-2,2) D10(-2,2.8) D11(-2,3.6) D12(-2,4.4) E1(-1.2,-4.4) E2(-1.2,-3.6) E3(-1.2,-2.8) E4(-1.2,-2) E5(-1.2,-1.2) E6(-1.2,-0.4) E7(-1.2,0.4) E8(-1.2,1.2) E9(-1.2,2) E10(-1.2,2.8) E11(-1.2,3.6) E12(-1.2,4.4) F1(-0.4,-4.4) F2(-0.4,-3.6) F3(-0.4,-2.8) F4(-0.4,-2) F5(-0.4,-1.2) F6(-0.4,-0.4) F7(-0.4,0.4) F8(-0.4,1.2) F9(-0.4,2) F10(-0.4,2.8) F11(-0.4,3.6) F12(-0.4,4.4) G1(0.4,-4.4) G2(0.4,-3.6) G3(0.4,-2.8) G4(0.4,-2) G5(0.4,-1.2) G6(0.4,-0.4) G7(0.4,0.4) G8(0.4,1.2) G9(0.4,2) G10(0.4,2.8) G11(0.4,3.6) G12(0.4,4.4) H1(1.2,-4.4) H2(1.2,-3.6) H3(1.2,-2.8) H4(1.2,-2) H5(1.2,-1.2) H6(1.2,-0.4) H7(1.2,0.4) H8(1.2,1.2) H9(1.2,2) H10(1.2,2.8) H11(1.2,3.6) H12(1.2,4.4) J1(2,-4.4) J2(2,-3.6) J3(2,-2.8) J4(2,-2) J5(2,-1.2) J6(2,-0.4) J7(2,0.4) J8(2,1.2) J9(2,2) J10(2,2.8) J11(2,3.6) J12(2,4.4) K1(2.8,-4.4) K2(2.8,-3.6) K3(2.8,-2.8) K4(2.8,-2) K5(2.8,-1.2) K6(2.8,-0.4) K7(2.8,0.4) K8(2.8,1.2) K9(2.8,2) K10(2.8,2.8) K11(2.8,3.6) K12(2.8,4.4) L1(3.6,-4.4) L2(3.6,-3.6) L3(3.6,-2.8) L4(3.6,-2) L5(3.6,-1.2) L6(3.6,-0.4) L7(3.6,0.4) L8(3.6,1.2) L9(3.6,2) L10(3.6,2.8) L11(3.6,3.6) L12(3.6,4.4) M1(4.4,-4.4) M2(4.4,-3.6) M3(4.4,-2.8) M4(4.4,-2) M5(4.4,-1.2) M6(4.4,-0.4) M7(4.4,0.4) M8(4.4,1.2) M9(4.4,2) M10(4.4,2.8) M11(4.4,3.6) M12(4.4,4.4)
C0201
  rect 0.305x0.406 smd: 1(-0.318,0) 2(0.318,0)
C0201#2
  rect 0.61x0.61 smd: 1(-0.495,0) 2(0.495,0)
C0402
  rect 0.61x0.61 smd: 1(-0.495,0) 2(0.495,0)
C0603
  rect 0.762x0.889 smd: 1(-0.699,0) 2(0.699,0)
C0603#2
  rect 1.092x1.194 smd: 1(-0.851,0) 2(0.851,0)
C0805
  rect 1.295x1.6 smd: 1(-0.953,0) 2(0.953,0)
C0805H53
  rect 1.295x1.6 smd: 1(-0.953,0) 2(0.953,0)
C0805H60
  rect 1.295x1.6 smd: 1(-0.953,0) 2(0.953,0)
C1206H71
  rect 1.6x2.007 smd: 1(-1.397,0) 2(1.397,0)
CNHDR1X1H344
  round 1.651 hole 1.143: 1(0,0)
CNHDR2X5H219
  rect 1.067x1.067 hole 0.711: 1(0,0)
  round 1.067 hole 0.711: 2(0,1.27) 3(1.27,0) 4(1.27,1.27) 5(2.54,0) 6(2.54,1.27) 7(3.81,0) 8(3.81,1.27) 9(5.08,0) 10(5.08,1.27)
CNMOLEX47590-0001
  oval 1.118x0.914 hole 0.864x0.66: (4.45,2.225) (4.45,-2.225)
  rect 1.346x0.406 smd: 1(4.123,-1.3) 2(4.123,-0.65) 3(4.123,0) 4(4.123,0.65) 5(4.123,1.3)
  custom 0.349x0.349 hole 1.295x0.61: SH1(1.45,4.175) SH3(1.45,-4.175)
  rect 1.905x2.896 smd: SH2(1.45,0)
CNSMARAL687W375H171
  rect 5.08x0.483 smd: 1(-0.254,0)
  rect 5.08x2.413 smd: 2(-0.254,4.381) 3(-0.254,4.381) 4(-0.254,-4.381) 5(-0.254,-4.381)
CSPBGA225
  round 0.305 smd: A1(-5.6,-5.6) A2(-5.6,-4.8) A3(-5.6,-4) A4(-5.6,-3.2) A5(-5.6,-2.4) A6(-5.6,-1.6) A7(-5.6,-0.8) A8(-5.6,0) A9(-5.6,0.8) A10(-5.6,1.6) A11(-5.6,2.4) A12(-5.6,3.2) A13(-5.6,4) A14(-5.6,4.8) A15(-5.6,5.6) B1(-4.8,-5.6) B2(-4.8,-4.8) B3(-4.8,-4) B4(-4.8,-3.2) B5(-4.8,-2.4) B6(-4.8,-1.6) B7(-4.8,-0.8) B8(-4.8,0) B9(-4.8,0.8) B10(-4.8,1.6) B11(-4.8,2.4) B12(-4.8,3.2) B13(-4.8,4) B14(-4.8,4.8) B15(-4.8,5.6) C1(-4,-5.6) C2(-4,-4.8) C3(-4,-4) C4(-4,-3.2) C5(-4,-2.4) C6(-4,-1.6) C7(-4,-0.8) C8(-4,0) C9(-4,0.8) C10(-4,1.6) C11(-4,2.4) C12(-4,3.2) C13(-4,4) C14(-4,4.8) C15(-4,5.6) D1(-3.2,-5.6) D2(-3.2,-4.8) D3(-3.2,-4) D4(-3.2,-3.2) D5(-3.2,-2.4) D6(-3.2,-1.6) D7(-3.2,-0.8) D8(-3.2,0) D9(-3.2,0.8) D10(-3.2,1.6) D11(-3.2,2.4) D12(-3.2,3.2) D13(-3.2,4) D14(-3.2,4.8) D15(-3.2,5.6) E1(-2.4,-5.6) E2(-2.4,-4.8) E3(-2.4,-4) E4(-2.4,-3.2) E5(-2.4,-2.4) E6(-2.4,-1.6) E7(-2.4,-0.8) E8(-2.4,0) E9(-2.4,0.8) E10(-2.4,1.6) E11(-2.4,2.4) E12(-2.4,3.2) E13(-2.4,4) E14(-2.4,4.8) E15(-2.4,5.6) F1(-1.6,-5.6) F2(-1.6,-4.8) F3(-1.6,-4) F4(-1.6,-3.2) F5(-1.6,-2.4) F6(-1.6,-1.6) F7(-1.6,-0.8) F8(-1.6,0) F9(-1.6,0.8) F10(-1.6,1.6) F11(-1.6,2.4) F12(-1.6,3.2) F13(-1.6,4) F14(-1.6,4.8) F15(-1.6,5.6) G1(-0.8,-5.6) G2(-0.8,-4.8) G3(-0.8,-4) G4(-0.8,-3.2) G5(-0.8,-2.4) G6(-0.8,-1.6) G7(-0.8,-0.8) G8(-0.8,0) G9(-0.8,0.8) G10(-0.8,1.6) G11(-0.8,2.4) G12(-0.8,3.2) G13(-0.8,4) G14(-0.8,4.8) G15(-0.8,5.6) H1(0,-5.6) H2(0,-4.8) H3(0,-4) H4(0,-3.2) H5(0,-2.4) H6(0,-1.6) H7(0,-0.8) H8(0,0) H9(0,0.8) H10(0,1.6) H11(0,2.4) H12(0,3.2) H13(0,4) H14(0,4.8) H15(0,5.6) J1(0.8,-5.6) J2(0.8,-4.8) J3(0.8,-4) J4(0.8,-3.2) J5(0.8,-2.4) J6(0.8,-1.6) J7(0.8,-0.8) J8(0.8,0) J9(0.8,0.8) J10(0.8,1.6) J11(0.8,2.4) J12(0.8,3.2) J13(0.8,4) J14(0.8,4.8) J15(0.8,5.6) K1(1.6,-5.6) K2(1.6,-4.8) K3(1.6,-4) K4(1.6,-3.2) K5(1.6,-2.4) K6(1.6,-1.6) K7(1.6,-0.8) K8(1.6,0) K9(1.6,0.8) K10(1.6,1.6) K11(1.6,2.4) K12(1.6,3.2) K13(1.6,4) K14(1.6,4.8) K15(1.6,5.6) L1(2.4,-5.6) L2(2.4,-4.8) L3(2.4,-4) L4(2.4,-3.2) L5(2.4,-2.4) L6(2.4,-1.6) L7(2.4,-0.8) L8(2.4,0) L9(2.4,0.8) L10(2.4,1.6) L11(2.4,2.4) L12(2.4,3.2) L13(2.4,4) L14(2.4,4.8) L15(2.4,5.6) M1(3.2,-5.6) M2(3.2,-4.8) M3(3.2,-4) M4(3.2,-3.2) M5(3.2,-2.4) M6(3.2,-1.6) M7(3.2,-0.8) M8(3.2,0) M9(3.2,0.8) M10(3.2,1.6) M11(3.2,2.4) M12(3.2,3.2) M13(3.2,4) M14(3.2,4.8) M15(3.2,5.6) N1(4,-5.6) N2(4,-4.8) N3(4,-4) N4(4,-3.2) N5(4,-2.4) N6(4,-1.6) N7(4,-0.8) N8(4,0) N9(4,0.8) N10(4,1.6) N11(4,2.4) N12(4,3.2) N13(4,4) N14(4,4.8) N15(4,5.6) P1(4.8,-5.6) P2(4.8,-4.8) P3(4.8,-4) P4(4.8,-3.2) P5(4.8,-2.4) P6(4.8,-1.6) P7(4.8,-0.8) P8(4.8,0) P9(4.8,0.8) P10(4.8,1.6) P11(4.8,2.4) P12(4.8,3.2) P13(4.8,4) P14(4.8,4.8) P15(4.8,5.6) R1(5.6,-5.6) R2(5.6,-4.8) R3(5.6,-4) R4(5.6,-3.2) R5(5.6,-2.4) R6(5.6,-1.6) R7(5.6,-0.8) R8(5.6,0) R9(5.6,0.8) R10(5.6,1.6) R11(5.6,2.4) R12(5.6,3.2) R13(5.6,4) R14(5.6,4.8) R15(5.6,5.6)
D0201
  rect 0.229x0.381 smd: A(0.22,0) C(-0.22,0)
DFN6_2X2_PAD1_6X1
  oval 0.305x0.864 smd: 1(-0.65,-1.082) 2(0,-1.082) 3(0.65,-1.082) 4(0.65,1.082) 5(0,1.082) 6(-0.65,1.082)
  rect 1.6x0.991 smd: PAD(0,0)
DIOSMJ5_0
  rect 2.286x1.88 smd: A(2.164,0) C(-2.164,0)
F0402H20
  rect 0.559x0.711 smd: 1(-0.49,0) 2(0.49,0)
FBGA96_C
  round 0.381 smd: A1(-6,-3.2) A2(-6,-2.4) A3(-6,-1.6) A7(-6,1.6) A8(-6,2.4) A9(-6,3.2) B1(-5.2,-3.2) B2(-5.2,-2.4) B3(-5.2,-1.6) B7(-5.2,1.6) B8(-5.2,2.4) B9(-5.2,3.2) C1(-4.4,-3.2) C2(-4.4,-2.4) C3(-4.4,-1.6) C7(-4.4,1.6) C8(-4.4,2.4) C9(-4.4,3.2) D1(-3.6,-3.2) D2(-3.6,-2.4) D3(-3.6,-1.6) D7(-3.6,1.6) D8(-3.6,2.4) D9(-3.6,3.2) E1(-2.8,-3.2) E2(-2.8,-2.4) E3(-2.8,-1.6) E7(-2.8,1.6) E8(-2.8,2.4) E9(-2.8,3.2) F1(-2,-3.2) F2(-2,-2.4) F3(-2,-1.6) F7(-2,1.6) F8(-2,2.4) F9(-2,3.2) G1(-1.2,-3.2) G2(-1.2,-2.4) G3(-1.2,-1.6) G7(-1.2,1.6) G8(-1.2,2.4) G9(-1.2,3.2) H1(-0.4,-3.2) H2(-0.4,-2.4) H3(-0.4,-1.6) H7(-0.4,1.6) H8(-0.4,2.4) H9(-0.4,3.2) J1(0.4,-3.2) J2(0.4,-2.4) J3(0.4,-1.6) J7(0.4,1.6) J8(0.4,2.4) J9(0.4,3.2) K1(1.2,-3.2) K2(1.2,-2.4) K3(1.2,-1.6) K7(1.2,1.6) K8(1.2,2.4) K9(1.2,3.2) L1(2,-3.2) L2(2,-2.4) L3(2,-1.6) L7(2,1.6) L8(2,2.4) L9(2,3.2) M1(2.8,-3.2) M2(2.8,-2.4) M3(2.8,-1.6) M7(2.8,1.6) M8(2.8,2.4) M9(2.8,3.2) N1(3.6,-3.2) N2(3.6,-2.4) N3(3.6,-1.6) N7(3.6,1.6) N8(3.6,2.4) N9(3.6,3.2) P1(4.4,-3.2) P2(4.4,-2.4) P3(4.4,-1.6) P7(4.4,1.6) P8(4.4,2.4) P9(4.4,3.2) R1(5.2,-3.2) R2(5.2,-2.4) R3(5.2,-1.6) R7(5.2,1.6) R8(5.2,2.4) R9(5.2,3.2) T1(6,-3.2) T2(6,-2.4) T3(6,-1.6) T7(6,1.6) T8(6,2.4) T9(6,3.2)
L0805
  rect 1.143x1.27 smd: 1(-0.953,0) 2(0.953,0)
L0805-4PH39
  rect 0.889x0.406 smd: 1(-0.845,-0.403) 2(0.845,-0.403) 3(0.845,0.403) 4(-0.845,0.403)
L0805-F
  rect 1.092x1.499 smd: 1(-1.046,0) 2(1.046,0)
L2020_A
  custom 0.425x0.425 smd: 1(-1.606,-1.501) 2(1.606,-1.501) 3(1.606,1.501) 4(-1.606,1.501)
LED0804
  rect 0.787x0.762 smd: A(1.1,0) C(-1.1,0)
LSMSQ79H41
  rect 1.041x2.21 smd: 1(-0.724,0) 2(0.724,0)
LSMSQ157H83
  rect 1.473x3.683 smd: 1(-1.232,0) 2(1.232,0)
MSOP8
  rect 0.305x1.321 smd: 1(-0.975,-2.3) 2(-0.325,-2.3) 3(0.325,-2.3) 4(0.975,-2.3) 5(0.975,2.3) 6(0.325,2.3) 7(-0.325,2.3) 8(-0.975,2.3)
QFN16_4X4_PAD2_1X2_1
  oval 0.356x1.041 smd: 1(-0.975,-1.9) 2(-0.325,-1.9) 3(0.325,-1.9) 4(0.975,-1.9) 9(0.975,1.9) 10(0.325,1.9) 11(-0.325,1.9) 12(-0.975,1.9)
  oval 1.041x0.356 smd: 5(1.9,-0.975) 6(1.9,-0.325) 7(1.9,0.325) 8(1.9,0.975) 13(-1.9,0.975) 14(-1.9,0.325) 15(-1.9,-0.325) 16(-1.9,-0.975)
  rect 2.108x2.108 smd: PAD(0,0)
QFN16_4X4_PAD2_5X2_5
  oval 0.356x0.991 smd: 1(-0.975,-1.974) 2(-0.325,-1.974) 3(0.325,-1.974) 4(0.975,-1.974) 9(0.975,1.974) 10(0.325,1.974) 11(-0.325,1.974) 12(-0.975,1.974)
  oval 0.991x0.356 smd: 5(1.974,-0.975) 6(1.974,-0.325) 7(1.974,0.325) 8(1.974,0.975) 13(-1.974,0.975) 14(-1.974,0.325) 15(-1.974,-0.325) 16(-1.974,-0.975)
  rect 2.489x2.489 smd: PAD(0,0)
QFN32_5X5_PAD3_1X3_1
  oval 0.305x0.889 smd: 1(-1.75,-2.45) 2(-1.25,-2.45) 3(-0.75,-2.45) 4(-0.25,-2.45) 5(0.25,-2.45) 6(0.75,-2.45) 7(1.25,-2.45) 8(1.75,-2.45) 17(1.75,2.45) 18(1.25,2.45) 19(0.75,2.45) 20(0.25,2.45) 21(-0.25,2.45) 22(-0.75,2.45) 23(-1.25,2.45) 24(-1.75,2.45)
  oval 0.889x0.305 smd: 9(2.45,-1.75) 10(2.45,-1.25) 11(2.45,-0.75) 12(2.45,-0.25) 13(2.45,0.25) 14(2.45,0.75) 15(2.45,1.25) 16(2.45,1.75) 25(-2.45,1.75) 26(-2.45,1.25) 27(-2.45,0.75) 28(-2.45,0.25) 29(-2.45,-0.25) 30(-2.45,-0.75) 31(-2.45,-1.25) 32(-2.45,-1.75)
  rect 3.099x3.099 smd: PAD(0,0)
QFN32_5X5_PAD3_3X3_3
  oval 0.305x0.889 smd: 1(-1.75,-2.45) 2(-1.25,-2.45) 3(-0.75,-2.45) 4(-0.25,-2.45) 5(0.25,-2.45) 6(0.75,-2.45) 7(1.25,-2.45) 8(1.75,-2.45) 17(1.75,2.45) 18(1.25,2.45) 19(0.75,2.45) 20(0.25,2.45) 21(-0.25,2.45) 22(-0.75,2.45) 23(-1.25,2.45) 24(-1.75,2.45)
  oval 0.889x0.305 smd: 9(2.45,-1.75) 10(2.45,-1.25) 11(2.45,-0.75) 12(2.45,-0.25) 13(2.45,0.25) 14(2.45,0.75) 15(2.45,1.25) 16(2.45,1.75) 25(-2.45,1.75) 26(-2.45,1.25) 27(-2.45,0.75) 28(-2.45,0.25) 29(-2.45,-0.25) 30(-2.45,-0.75) 31(-2.45,-1.25) 32(-2.45,-1.75)
  rect 3.302x3.302 smd: PAD(0,0)
R0201
  rect 0.305x0.406 smd: 1(-0.318,0) 2(0.318,0)
R0402
  rect 0.61x0.61 smd: 1(-0.495,0) 2(0.495,0)
R0603
  rect 0.889x0.813 smd: 1(-0.737,0) 2(0.737,0)
R0603#2
  rect 0.711x0.914 smd: 1(-0.6,0) 2(0.6,0)
R0805
  rect 1.295x1.397 smd: 1(-0.953,0) 2(0.953,0)
RM10
  rect 0.305x1.321 smd: 1(-1,-2.171) 2(-0.5,-2.171) 3(0,-2.171) 4(0.5,-2.171) 5(1,-2.171) 6(1,2.171) 7(0.5,2.171) 8(0,2.171) 9(-0.5,2.171) 10(-1,2.171)
SON10_2X2_PAD1_5X0_9
  oval 0.203x0.762 smd: 1(-0.8,-1) 2(-0.4,-1) 3(0,-1) 4(0.4,-1) 5(0.8,-1) 6(0.8,1) 7(0.4,1) 8(0,1) 9(-0.4,1) 10(-0.8,1)
  rect 1.499x0.889 smd: PAD(0,0)
SOT23
  rect 1.016x1.397 smd: 1(-0.94,-1.118) 2(0.94,-1.118) 3(0,1.118)
SWSML140W138H55
  round 0.889 hole 0.711 unplated: (-0.9,0) (0.9,0)
  rect 1.041x1.397 smd: 1(-0.721,-1.799) 2(-0.721,1.799) 3(0.721,-1.799) 4(0.721,1.799)
  rect 0.508x1.092 smd: 5(-1.704,0)
TBGA24
  round 0.33 smd: A2(-2,-1) A3(-2,0) A4(-2,1) A5(-2,2) B1(-1,-2) B2(-1,-1) B3(-1,0) B4(-1,1) B5(-1,2) C1(0,-2) C2(0,-1) C3(0,0) C4(0,1) C5(0,2) D1(1,-2) D2(1,-1) D3(1,0) D4(1,1) D5(1,2) E1(2,-2) E2(2,-1) E3(2,0) E4(2,1) E5(2,2)
TPC75D45
  round 1.905 hole 1.143: 1(0,0)
TPSMC40
  round 1.905 hole 1.143: 1(0,0)
TSML150W160H160
  rect 0.762x1.651 smd: 1(-1.27,1.587) 2(0,1.587) 3(1.27,1.587) 4(1.27,-1.587) 5(0,-1.587) 6(-1.27,-1.587)
unnamed
  round 0.889 hole 0.635 unplated: (0,0)
unnamed#3
  round 1.016 hole 0.508: 1(0,0)
WLCSP4-2
  round 0.254 smd: A1(-0.25,-0.25) A2(-0.25,0.25) B1(0.25,-0.25) B2(0.25,0.25)
WLCSP6
  round 0.254 smd: A1(-0.5,-0.25) A2(-0.5,0.25) B1(0,-0.25) B2(0,0.25) C1(0.5,-0.25) C2(0.5,0.25)
YSML98W79H35
  rect 1.092x0.991 smd: 1(-0.921,-0.72) 2(0.921,-0.72) 3(0.921,0.72) 4(-0.921,0.72)
YSML126W98H47
  rect 1.397x1.194 smd: 1(-1.2,-0.95) 2(1.2,-0.95) 3(1.2,0.95) 4(-1.2,0.95)

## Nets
1V8: C1.1(N1) C10.1(N1) C22.1(N1) C25.1(N1) C46.1(N1) C48.1(N1) C49.1(N1) C50.1(N1) C51.1(N1) C52.1(N1) C53.1(N1) C65.1(N1) C67.1(N1) C69.1(N1) C76.1(N1) C77.1(N1) C78.1(N1) C82.1(N1) C83.1(N1) C90.1(N1) C103.1(N1) C104.1(N1) C105.1(N1) C106.1(N1) C107.1(N1) C108.1(N1) C109.1(N1) C110.1(N1) C111.1(N1) C112.1(N1) C113.1(N1) C114.1(N1) C115.1(N1) C116.1(N1) C117.1(N1) C118.1(N1) C119.1(N1) C120.1(N1) C140.1(N1) C149.1(N1) C150.1(N1) C152.1(N1) C153.1(N1) C154.1(N1) C158.1(N1) C159.1(N1) C160.1(N1) C161.1(N1) C162.1(N1) C163.2(N2) C166.2(N2) C168.1(N1) C174.1(N1) E1.1(N1) E4.1(N1) E5.1(N1) L5.2(N2) P1.10(N5) R8.1(N1) R11.1(N1) R13.1(N1) R14.1(N1) R44.1(N1) R45.1(N1) R46.2(N2) R47.2(N2) R50.2(N2) R57.1(N1) R64.2(N2) R74.1(N1) R76.1(N1) R78.1(N1) R79.1(N1) R83.1(N1) R84.2(N2) R122.2(N2) U1.1(VIN1) U1.2(VIN2) U1.3(VIN3) U1.15(VIN4) U1.16(VIN5) U4.A6(VCCO_MIO0_500_1) U4.B13(VCCO_MIO1_501_1) U4.C10(VCCO_MIO1_501_2) U4.D7(VCCO_MIO0_500_2) U4.E14(VCCO_MIO1_501_3) U4.F11(VCCO_34_6) U4.G4(RSVDVCC1) U4.H4(RSVDVCC3) U4.H9(VCCAUX_1) U4.H15(VCCO_34_7) U4.J4(RSVDVCC2) U4.J6(VCCPAUX_1) U4.J8(VCCAUX_2) U4.J12(VCCO_34_1) U4.K8(VCCO_0) U4.K9(VCCAUX_3) U4.L6(VCCPAUX_2) U4.M13(VCCO_34_2) U4.N10(VCCO_34_3) U4.P7(VCCO_34_4) U4.R14(VCCO_34_5) U7.1(VIN1) U7.2(VIN2) U7.3(VIN3) U7.15(VIN4) U7.16(VIN5) U11.1(VCCA) U13.B4(VCC) U15.8(REFSEL0) U15.11(REFSEL1) U15.14(REFSEL2) U15.28(VDD18_1) U15.30(VDD18_2) U15.32(VDDIO) UNK1V8.1 UNK1V8#2.1 Y1.4(VDD) Y2.4(VDD)
1V35: C54.1(N1) C55.1(N1) C56.1(N1) C57.1(N1) C58.1(N1) C59.1(N1) C60.1(N1) C61.1(N1) C86.1(N1) C87.1(N1) C88.1(N1) C89.1(N1) C91.1(N1) C92.1(N1) C94.1(N1) C95.1(N1) C96.1(N1) C97.1(N1) C100.1(N1) C145.1(N1) C148.1(N1) C151.1(N1) L2.2(N2) R41.2(N2) R62.1(N1) U2.A1(VDDQ_1) U2.A8(VDDQ_2) U2.B2(VDD_1) U2.C1(VDDQ_3) U2.C9(VDDQ_4) U2.D2(VDDQ_5) U2.D9(VDD_2) U2.E9(VDDQ_6) U2.F1(VDDQ_7) U2.G7(VDD_3) U2.H2(VDDQ_8) U2.H9(VDDQ_9) U2.K2(VDD_4) U2.K8(VDD_5) U2.N1(VDD_6) U2.N9(VDD_7) U2.R1(VDD_8) U2.R9(VDD_9) U4.B3(VCCO_DDR_502_1) U4.E4(VCCO_DDR_502_2) U4.F1(VCCO_DDR_502_3) U4.J2(VCCO_DDR_502_4) U4.M3(VCCO_DDR_502_5) U4.R4(VCCO_DDR_502_6) U14.1(VDDQSNS) UNK1V35.1
